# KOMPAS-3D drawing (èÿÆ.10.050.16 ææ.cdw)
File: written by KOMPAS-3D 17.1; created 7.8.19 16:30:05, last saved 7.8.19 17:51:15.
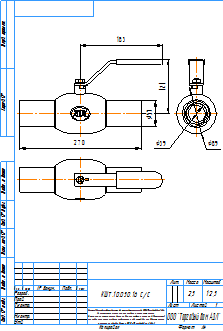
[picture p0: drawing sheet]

Sheet 1: A4, portrait

Title block, sheet 1: name: КШТ.10.050.16 С/С; material: Сталь 20  ГОСТ 1050-2013; mass: 2,5; sheets: 1; sheet format: A4; stored path: C:\Users\kka\KOMPAS_Work\Модели кранов для исследований\DN65\КШТ.10.065.16 СС.cdw

Views: Вид 1, Проекционный вид 2, Проекционный вид 3
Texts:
  kka
  adl
  Рама для чертежей
  Лит-Масса-Масштаб
  Материал-Предприятие
  Масштаб
  Изм.
  Лист
  № докум.
  Подп.
  Дата
  Лит.
  Разраб.
  Пров.
  Т.контр.
  Листов
  Внимание! Данный продукт является объектом авторского права ООО «Торговый Дом АДЛ».
  Запрещается изменение, копирование, распространение
  (в том числе путем копирования на другие сайты и ресурсы в Интернете)
  или любое иное использование информации и объектов без предварительного
  согласия правообладателя (ООО «Торговый Дом АДЛ»).
  Н.контр.
  Утв.
  ООО "Торговый дом АДЛ"
  Изменение
  Номер документа
  Подпись
  Обозначение документа
  Наименование изделия
  Масса изделия по ГОСТ 2.109-73
  Порядковый номер листа
  Общее количество листов в документе
  Характер работы, выполненной лицом, подписавшим документ
  Наименование или индекс предприятия, выпускающего документ
  Инв. № подл.
  Подп. и дата
  Взам. инв. №
  Инв. № дубл.
  Инвентарный номер подлинника по ГОСТ 2.501-68
  Подпись принявшего подлинник в отдел технической документации
  Инвентарный номер подлинника, взамен которого выпущен данный подлинник
  Инвентарный номер дубликата по ГОСТ 2.502-68
  Подпись принявшего дубликат в отдел технической документации
  Справ. №
  Перв. примен.
  Обозначение документа, взамен или на основании которого выпущен данный документ
  Обозначение документа, в котором впервые записан данный документ
  Подпись лица, копировавшего чертеж
  Обозначение формата листа
  !Рама для чертежа
Dimensions and other numbers on the sheet: 270; 183; 121; 57; 89; 39; 1:2,5; 1; 2,5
